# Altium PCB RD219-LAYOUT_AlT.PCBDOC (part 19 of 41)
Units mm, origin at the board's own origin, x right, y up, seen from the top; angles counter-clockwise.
Board outline 209.75 x 159.97 mm, 2 copper layers (TOP, BOTTOM), stack 0 mm thick; 398 components, 199 nets, 1469 pads, 0 vias.
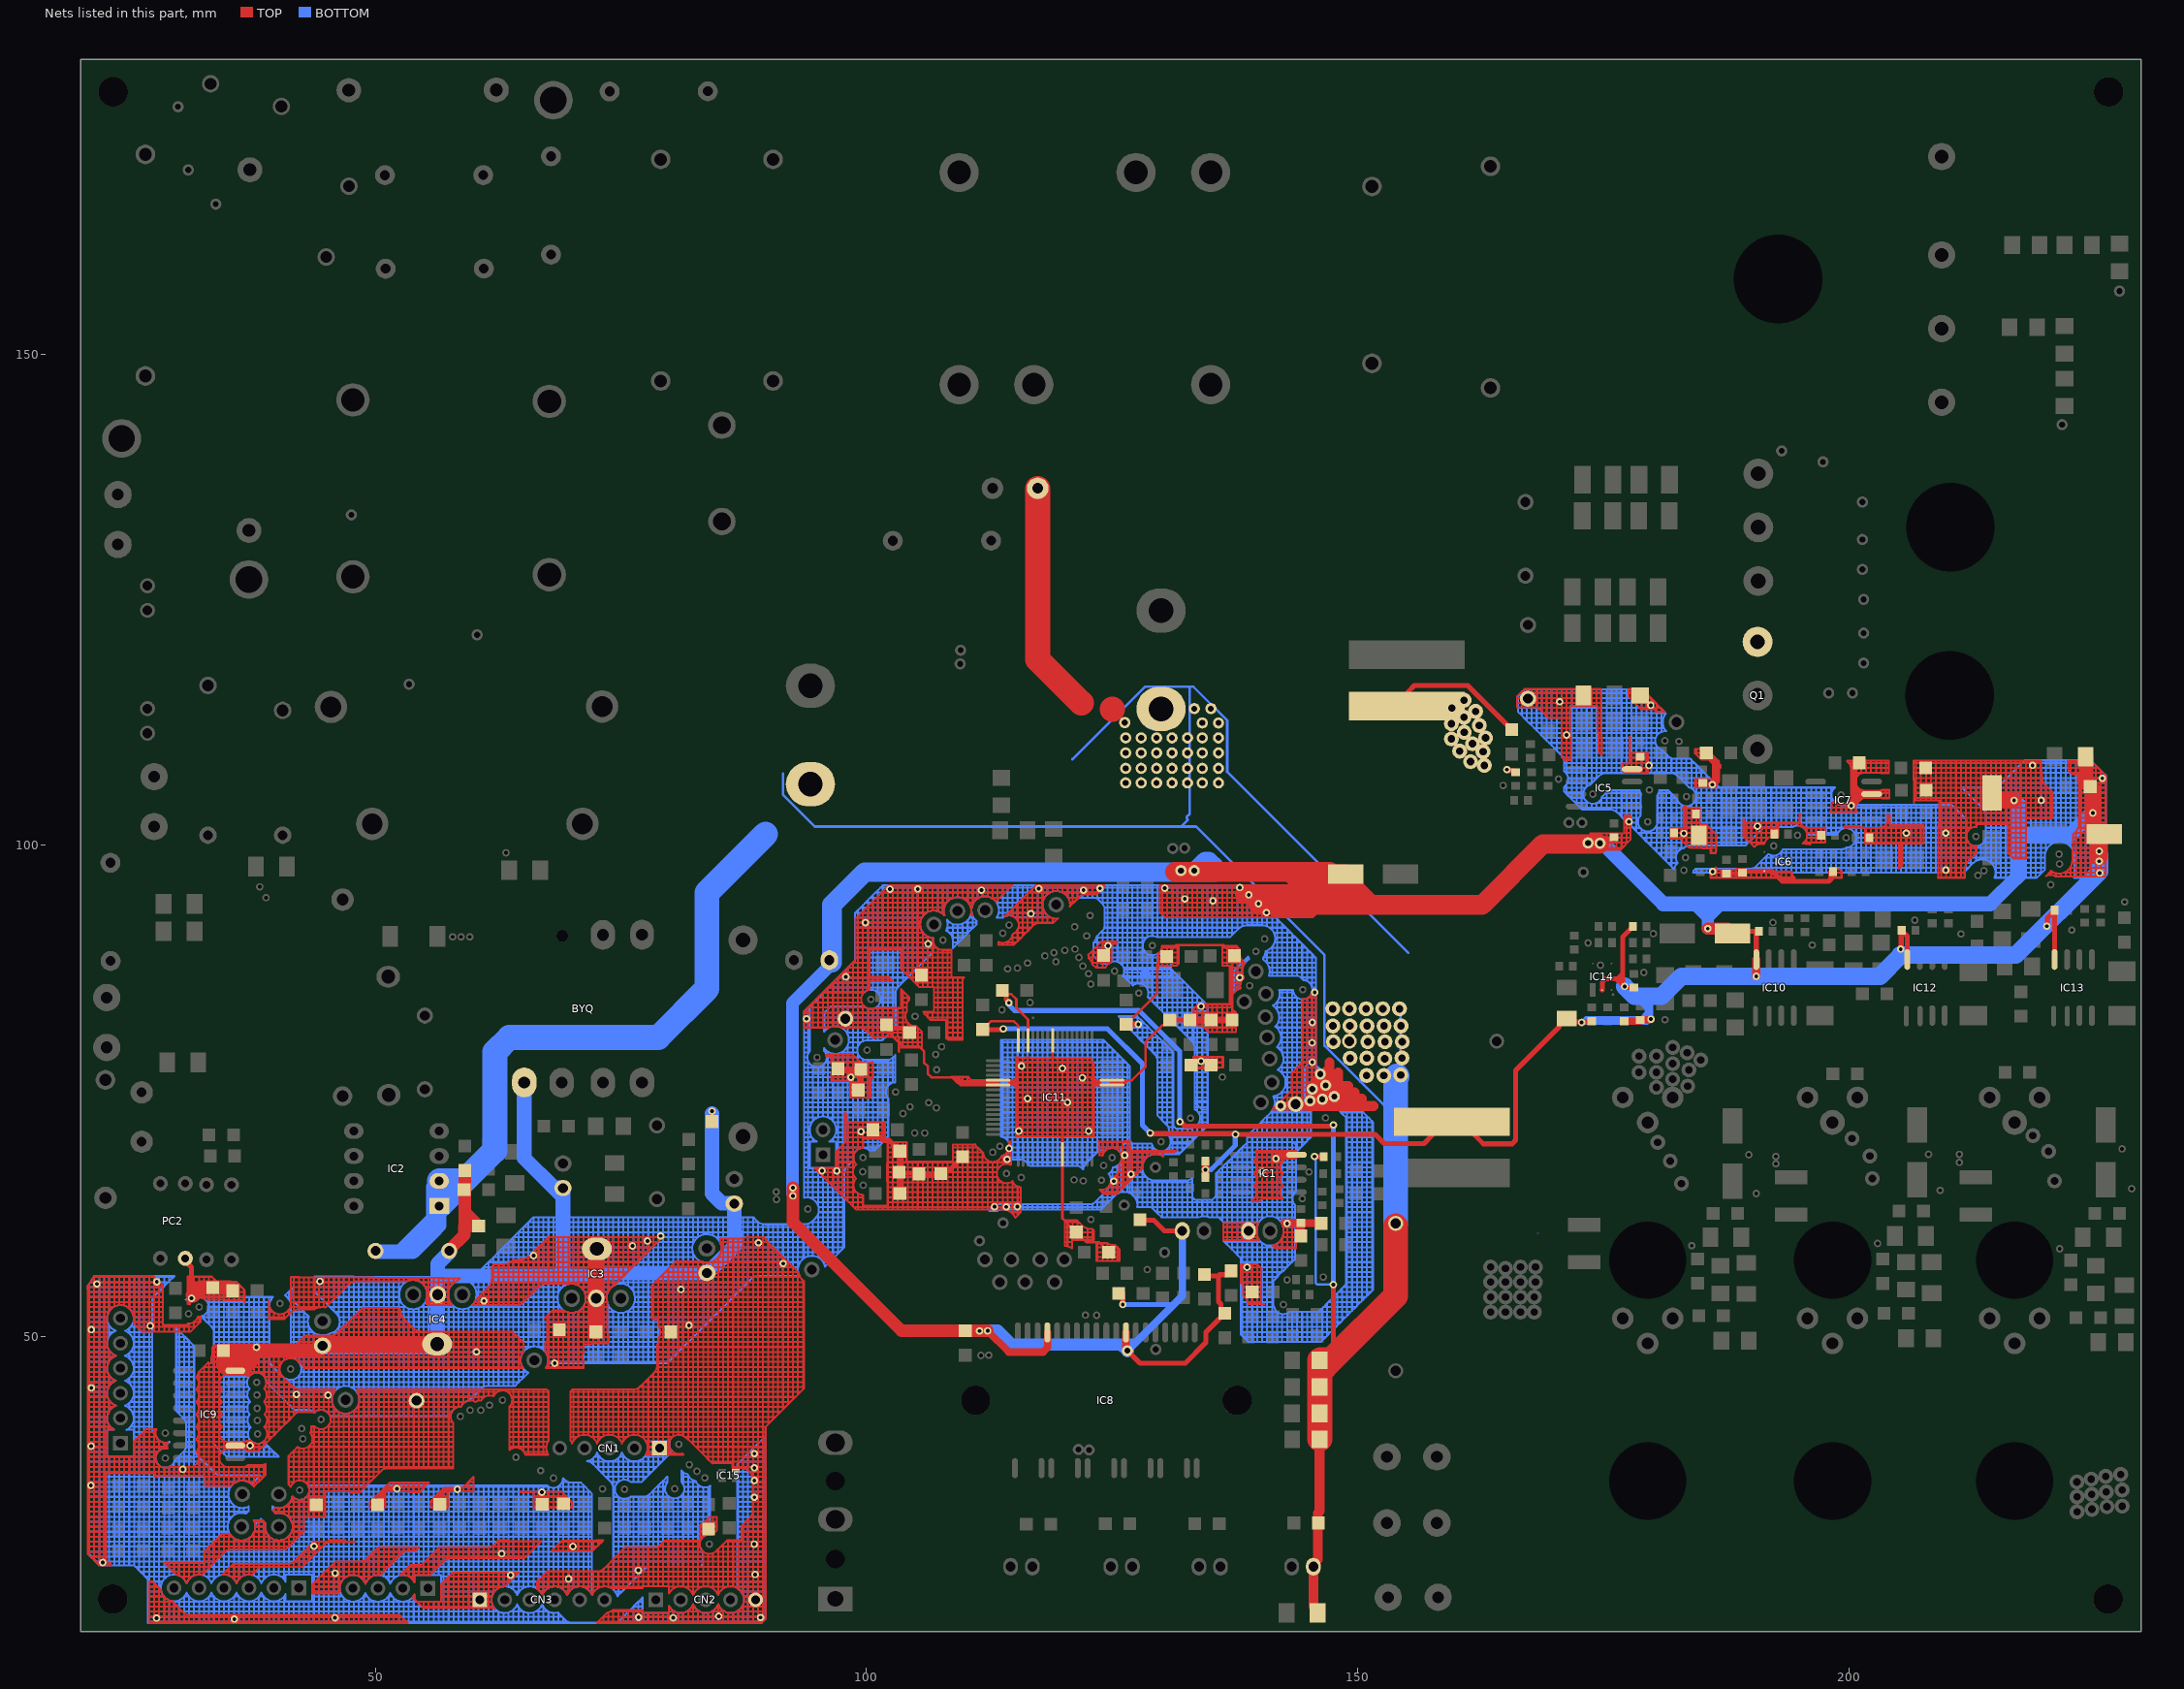
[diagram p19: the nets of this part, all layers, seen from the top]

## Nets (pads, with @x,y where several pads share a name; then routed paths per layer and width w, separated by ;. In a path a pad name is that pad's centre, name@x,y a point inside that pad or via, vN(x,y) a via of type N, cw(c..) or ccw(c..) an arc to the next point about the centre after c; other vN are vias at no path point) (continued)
GND: (continued)
  BOTTOM w0.203: 20.889,27.877 20.889,28.128 ; 21.318,56.068 21.397,56.068 ; 22.765,41.344 ccw(c24.064,41.717) 22.767,41.336 ; 22.765,43.884 ccw(c24.064,44.257) 22.767,43.876 ; 22.765,46.424 ccw(c24.064,46.797) 22.767,46.416 ; 22.765,48.964 ccw(c24.064,49.337) 22.767,48.956 ; 22.765,51.504 ccw(c24.064,51.877) 22.767,51.496 ; 22.771,41.322 cw(c24.064,41.717) 22.767,41.336 ; 22.771,43.862 cw(c24.064,44.257) 22.767,43.876 ; 22.771,46.402 cw(c24.064,46.797) 22.767,46.416 ; 22.771,48.942 cw(c24.064,49.337) 22.767,48.956 ; 22.771,51.482 cw(c24.064,51.877) 22.767,51.496 ; 22.918,52.593 ccw(c24.064,51.877) 22.871,52.512 ; 22.921,52.598 22.921,53.02 ; 22.93,52.613 cw(c24.064,51.877) 23.343,53.02 ; 23.409,40.535 cw(c24.064,41.717) 23.046,40.828 ; 23.42,40.529 22.921,40.529 ; 23.923,53.221 cw(c24.064,51.877) 23.937,53.223 ; 23.946,53.223 ccw(c24.064,51.877) 23.937,53.223 ; 24.699,40.524 ccw(c24.064,41.717) 24.708,40.529 ; 25.068,40.813 cw(c24.064,41.717) 24.953,40.699 ; 25.082,40.828 25.461,40.828 ; 25.084,40.83 ccw(c24.064,41.717) 25.361,41.336 ; 25.357,46.402 cw(c24.064,46.797) 25.082,45.908 ; 25.361,46.416 25.461,46.416 ; 25.363,46.424 ccw(c24.064,46.797) 25.416,46.797 ccw(c24.064,46.797) 25.41,46.924 ; 27.526,40.099 cw(c28.128,40.701) 27.493,40.134 ; 27.527,54.131 27.94,54.544 ; 27.536,40.088 cw(c28.128,40.701) 27.528,40.097 ; 27.661,37.773 ccw(c28.636,37.653) 27.73,37.272 ; 27.662,37.78 27.493,37.78 ; 27.663,37.79 cw(c28.636,37.653) 27.886,38.288 ; 27.687,39.939 ccw(c28.636,40.193) 27.687,39.937 ; 28.332,25.08 ccw(c29.525,24.445) 28.179,24.572 ; 28.382,38.602 ccw(c28.636,37.653) 28.38,38.602 ; 28.505,25.332 ccw(c29.525,24.445) 28.332,25.08 28.001,25.08 ; 28.509,25.336 28.509,25.588 ; 28.509,38.73 28.509,38.796 ; 28.509,56.172 28.509,56.068 ; 28.521,25.349 cw(c29.525,24.445) 28.804,25.588 ; 28.575,38.796 28.509,38.796 ; 29.051,36.762 ccw(c28.636,37.653) 29.055,36.764 ; 29.051,39.302 cw(c28.636,40.193) 28.509,39.219 ; 29.054,39.276 28.38,38.602 ; 29.067,36.77 cw(c28.636,37.653) 29.055,36.764 ; 29.464,56.068 29.017,56.068 ; 29.585,37.399 cw(c28.636,37.653) 29.585,37.397 ; 30.241,25.591 ccw(c29.525,24.445) 30.033,25.698 ; 30.246,25.588 30.541,25.588 ; 30.261,25.579 cw(c29.525,24.445) 30.541,25.336 ; 30.507,38.32 30.475,38.288 ; 30.507,41.685 30.348,41.844 ; 30.701,53.754 pad.@30.983,54.036 ; 30.718,53.754 pad.@31.049,53.754 ; 31.045,25.332 ccw(c32.065,24.445) 30.872,25.08 ; 31.049,25.336 31.049,25.588 ; 31.061,25.349 cw(c32.065,24.445) 31.344,25.588 ; pad.@31.412,53.754 pad.@31.049,53.754 ; pad.@31.414,53.756 cw(c32.071,53.026) pad.@31.557,53.863 ; 32.781,25.591 ccw(c32.065,24.445) 32.573,25.698 ; 32.786,25.588 33.081,25.588 ; 32.801,25.579 cw(c32.065,24.445) 33.081,25.336 ; 32.904,52.505 ccw(c32.071,53.026) 32.909,52.512 ; 32.913,52.519 cw(c32.071,53.026) 32.909,52.512 ; 33.585,25.332 ccw(c34.605,24.445) 33.412,25.08 ; 33.589,25.336 33.589,25.588 ; 33.601,25.349 cw(c34.605,24.445) 33.884,25.588 ; 35.109,33.607 cw(c36.463,33.97) 35.085,33.716 ; 35.113,30.076 cw(c36.383,30.668) 35.077,30.16 ; 35.113,31.26 ccw(c36.383,30.668) 35.077,31.176 ; 35.113,33.593 35.113,33.208 ; 35.116,33.584 ccw(c36.463,33.97) 35.287,33.208 ; 35.321,25.591 ccw(c34.605,24.445) 35.113,25.698 ; 35.326,25.588 35.621,25.588 ; 35.341,25.579 cw(c34.605,24.445) 35.621,25.336 ; 35.62,31.843 ccw(c36.383,30.668) 35.417,31.684 ; 35.621,31.844 35.621,32.192 ; 35.64,31.857 cw(c36.383,30.668) 36.129,32.046 ; 35.871,32.7 ccw(c36.463,33.97) 36.124,32.61 ccw(c36.463,33.97) 36.129,32.609 ; 36.116,29.292 cw(c36.383,30.668) 35.621,29.492 ; 36.116,32.044 cw(c36.383,30.668) 36.129,32.046 ; 36.125,25.332 ccw(c37.145,24.445) 35.952,25.08 ; 36.129,25.336 36.129,25.588 ; 36.129,29.29 36.129,29.144 ; 36.14,29.288 ccw(c36.383,30.668) 36.637,29.29 ; 36.14,32.048 ccw(c36.383,30.668) 36.129,32.046 ; 36.141,25.349 cw(c37.145,24.445) 36.424,25.588 ; 36.839,31.993 ccw(c36.383,30.668) 36.637,32.046 ; 36.843,31.992 37.044,32.192 ; 37.022,41.348 cw(c37.995,41.485) 37.081,41.844 ; 37.025,41.331 ccw(c37.995,41.485) 37.145,40.992 ; 37.024,41.336 36.637,41.336 ; 37.121,32.732 cw(c36.463,33.97) 37.115,32.729 ; 37.145,45.951 cw(c37.93,45.359) 37.653,46.302 ; 37.203,44.694 ccw(c37.967,44.076) 37.145,44.615 ; 37.209,42.094 cw(c37.973,42.712) 37.145,42.183 ; 37.212,44.689 cw(c37.93,45.359) 37.145,44.769 ; 37.221,42.09 ccw(c37.995,41.485) 37.145,41.978 ; 37.26,43.393 cw(c37.967,44.076) 37.145,43.537 ; 37.266,43.395 ccw(c37.973,42.712) 37.241,43.368 ; 37.305,40.78 ccw(c38.024,40.11) 37.145,40.55 ; 37.312,40.778 cw(c37.995,41.485) 37.264,40.828 ; 37.401,35.012 ccw(c36.463,33.97) 37.145,35.194 ; 37.406,35.007 37.639,35.24 ; 37.653,30.076 ccw(c36.383,30.668) 37.689,30.16 ; 37.771,30.863 cw(c36.383,30.668) 37.772,30.859 ; 37.861,25.591 ccw(c37.145,24.445) 37.653,25.698 ; 37.866,25.588 38.161,25.588 ; 37.881,25.579 cw(c37.145,24.445) 38.161,25.336 ; 38.147,35.748 37.653,35.748 ; 38.151,46.317 cw(c37.93,45.359) 38.161,46.314 ; 38.16,39.137 cw(c38.024,40.11) 37.655,39.199 cw(c38.024,40.11) 37.653,39.2 ; 38.168,46.313 ccw(c37.93,45.359) 38.161,46.314 ; 38.359,31.446 38.161,31.249 ; 38.371,31.459 38.655,31.176 ; 38.628,39.336 cw(c38.024,40.11) 38.625,39.333 ; 38.665,25.332 ccw(c39.685,24.445) 38.492,25.08 ; 38.669,25.336 38.669,25.588 ; 38.681,25.349 cw(c39.685,24.445) 38.964,25.588 ; 38.822,30.959 ccw(c40.193,30.668) 38.791,30.668 ; 38.827,30.983 cw(c40.193,30.668) 38.831,30.999 ; 38.833,31.007 ccw(c40.193,30.668) 38.831,30.999 ; 38.885,30.166 ccw(c40.193,30.668) 38.887,30.16 ; 38.893,30.143 cw(c40.193,30.668) 38.887,30.16 ; 38.912,45.408 39.177,45.143 ; 38.911,45.411 ccw(c37.93,45.359) 38.745,45.908 ; 38.92,45.4 39.177,45.4 ; 39.168,29.712 cw(c40.193,30.668) 38.887,30.16 ; 39.177,29.702 39.177,29.652 ; 39.185,29.694 ccw(c40.193,30.668) 39.227,29.652 ; 39.322,53.613 ccw(c40.32,53.147) 39.286,53.528 ; 39.33,53.63 cw(c40.32,53.147) 39.362,53.692 ; 39.362,53.69 cw(c40.296,53.386) 39.362,53.692 ; 39.366,53.698 ccw(c40.32,53.147) 39.362,53.692 ; 39.525,32.738 39.525,32.367 39.685,32.206 ; 39.535,32.732 ccw(c40.193,33.97) 39.685,32.664 ; 39.542,46.99 39.608,46.924 ; 39.59,54.069 ccw(c40.296,53.386) 39.559,54.036 ; 39.594,54.073 39.177,54.073 ; 39.854,32.028 cw(c40.193,30.668) 39.862,32.03 ; 40.401,25.591 ccw(c39.685,24.445) 40.193,25.698 ; 40.406,25.588 40.701,25.588 ; 40.421,25.579 cw(c39.685,24.445) 40.701,25.336 ; 40.785,32.7 cw(c40.193,33.97) 40.701,32.664 ; 40.817,54.22 cw(c40.296,53.386) 41.034,54.036 ; 40.878,23.81 cw(c39.685,24.445) 40.873,23.801 ; 40.878,25.08 ccw(c39.685,24.445) 40.873,25.089 ; 40.923,54.324 41.143,54.544 ; 41.151,53.87 cw(c40.32,53.147) 41.153,53.868 ; 41.156,53.863 ccw(c40.296,53.386) 41.153,53.868 ; 41.201,31.642 ccw(c40.193,30.668) 41.159,31.684 ; 41.209,31.634 41.209,31.684 ; 41.209,54.61 41.209,54.544 ; 41.218,31.624 cw(c40.193,30.668) 41.499,31.176 ; 41.493,30.143 cw(c40.193,30.668) 41.209,29.702 ; 41.499,30.16 41.717,30.16 ; 41.502,30.166 ccw(c40.193,30.668) 41.595,30.668 ; 41.573,33.727 cw(c40.193,33.97) 41.369,33.208 ; 41.577,33.732 ccw(c42.307,34.389) 41.717,33.604 ; 41.717,42.603 41.717,42.86 ; 41.955,53.329 42.225,53.059 ; 42.264,53.02 42.225,53.02 ; 43.149,51.508 ccw(c44.575,51.583) 43.15,51.496 ; 43.151,51.483 cw(c44.575,51.583) 43.15,51.496 ; 43.166,34.866 43.241,34.866 ; 43.167,34.866 cw(c42.307,34.389) 43.228,34.732 ; 43.225,52.048 ccw(c44.575,51.583) 43.211,52.004 ; 43.228,52.056 42.772,52.512 ; 43.715,42.352 43.749,42.352 ; 43.749,42.318 43.749,42.352 ; 43.785,42.282 43.708,42.359 ; 43.788,42.285 cw(c44.482,41.59) 43.862,42.352 ; 44.257,54.143 44.257,54.544 ; 44.257,56.12 44.257,56.068 ; 44.765,53.635 44.765,54.036 ; 45.4,41.942 ccw(c44.482,41.59) 45.273,42.173 ; 45.401,41.938 45.781,41.938 ; 45.445,50.368 ccw(c45.273,51.456) 45.452,50.369 ; 45.458,50.373 cw(c44.702,51.583) 45.452,50.369 ; 45.773,50.474 cw(c45.273,51.456) 45.452,50.369 ; 45.778,42.855 ccw(c46.979,43.576) 45.781,42.849 ; 45.778,44.298 ccw(c46.979,43.576) 45.61,43.876 ; 45.781,44.304 45.781,44.384 ; 45.781,50.479 45.781,49.972 ; 45.784,50.48 46.289,50.48 ; 45.79,42.834 cw(c46.979,43.576) 45.781,42.849 ; 45.79,44.319 cw(c46.979,43.576) 45.833,44.384 ; 45.79,50.483 ccw(c45.273,51.456) 46.27,50.988 ; 46.278,42.363 cw(c46.979,43.576) 45.781,42.849 ; 46.289,42.357 46.289,42.352 ; 46.297,42.352 46.289,42.352 ; 46.3,42.351 ccw(c46.979,43.576) 46.797,42.187 ; 46.387,24.562 ccw(c47.729,24.397) 46.419,24.064 ; 46.389,24.572 46.289,24.572 ; 46.39,24.585 cw(c47.729,24.397) 46.443,24.815 ; 46.417,24.07 ccw(c47.729,24.397) 46.419,24.064 ; 46.423,24.047 cw(c47.729,24.397) 46.419,24.064 ; 46.436,24.792 cw(c47.729,24.397) 46.558,25.073 cw(c47.729,24.397) 46.562,25.08 ; 46.784,44.964 cw(c46.979,43.576) 46.797,44.966 ; 46.79,25.369 ccw(c47.729,24.397) 46.562,25.08 ; 46.797,25.376 46.797,25.588 ; 46.807,25.386 cw(c47.729,24.397) 47.09,25.588 ; 46.808,44.968 ccw(c46.979,43.576) 46.797,44.966 ; 47.289,23.119 cw(c47.729,24.397) 46.797,23.418 ; 47.294,42.211 ccw(c46.979,43.576) 47.305,42.213 ; 47.305,23.114 47.305,23.048 ; 47.311,23.112 ccw(c47.729,24.397) 47.645,23.048 ; 47.318,42.217 cw(c46.979,43.576) 47.305,42.213 ; 47.458,44.894 ccw(c46.979,43.576) 47.305,44.94 ; 47.463,44.892 47.813,44.892 ; 47.481,44.885 cw(c46.979,43.576) 47.813,44.703 ; 47.8,25.747 cw(c47.729,24.397) 47.813,25.746 ; 47.803,42.443 cw(c46.979,43.576) 47.661,42.352 ; 47.812,23.048 cw(c47.729,24.397) 47.645,23.048 ; 47.813,42.45 47.813,42.352 ; 47.823,25.745 ccw(c47.729,24.397) 47.813,25.746 ; 47.823,42.457 ccw(c46.979,43.576) 48.184,42.86 ; 48.18,42.855 ccw(c46.979,43.576) 48.184,42.86 ; 48.193,42.876 cw(c46.979,43.576) 48.184,42.86 ; 48.363,25.59 ccw(c47.729,24.397) 48.321,25.612 ; 48.368,25.588 48.829,25.588 ; 48.384,25.579 cw(c47.729,24.397) 48.829,25.182 ; 48.822,23.603 ccw(c47.729,24.397) 48.829,23.612 ; 48.836,23.622 cw(c47.729,24.397) 48.829,23.612 ; 48.991,23.913 cw(c47.729,24.397) 48.829,23.612 ; 48.999,23.935 ccw(c50.269,24.397) 49.211,23.556 ; 49.33,25.369 ccw(c50.269,24.397) 49.102,25.08 ; 49.337,25.376 49.337,25.588 ; 49.347,25.386 cw(c50.269,24.397) 49.63,25.588 ; 49.829,23.119 cw(c50.269,24.397) 49.337,23.418 ; 49.845,23.114 49.845,23.048 ; 49.851,23.112 ccw(c50.269,24.397) 50.185,23.048 ; 50.34,25.747 cw(c50.269,24.397) 50.353,25.746 ; 50.352,23.048 cw(c50.269,24.397) 50.185,23.048 ; 50.363,25.745 ccw(c50.269,24.397) 50.353,25.746 ; 50.903,25.59 ccw(c50.269,24.397) 50.861,25.612 ; 50.908,25.588 51.369,25.588 ; 50.924,25.579 cw(c50.269,24.397) 51.369,25.182 ; 51.362,23.603 ccw(c50.269,24.397) 51.369,23.612 ; 51.376,23.622 cw(c50.269,24.397) 51.369,23.612 ; 51.531,23.913 cw(c50.269,24.397) 51.369,23.612 ; 51.539,23.935 ccw(c52.809,24.397) 51.744,23.565 ccw(c52.809,24.397) 51.751,23.556 ; 51.87,25.369 ccw(c52.809,24.397) 51.642,25.08 ; 51.877,25.376 51.877,25.588 ; 51.887,25.386 cw(c52.809,24.397) 52.17,25.588 ; 52.369,23.119 cw(c52.809,24.397) 51.877,23.418 ; 52.385,23.114 52.385,23.048 ; 52.391,23.112 ccw(c52.809,24.397) 52.725,23.048 ; 52.88,25.747 cw(c52.809,24.397) 52.893,25.746 ; 52.889,55.397 ccw(c53.862,54.354) 52.618,55.052 ; 52.892,23.048 cw(c52.809,24.397) 52.725,23.048 ; 52.893,55.401 52.893,55.56 ; 52.903,25.745 ccw(c52.809,24.397) 52.893,25.746 ; 52.907,55.414 cw(c53.862,54.354) 53.1,55.56 ; 53.085,53.03 cw(c53.862,54.227) 52.893,53.179 ; 53.1,53.02 52.893,53.02 ; 53.106,53.016 ccw(c53.862,54.227) 53.397,52.877 ccw(c53.862,54.227) 53.401,52.876 ; 53.443,25.59 ccw(c52.809,24.397) 53.401,25.612 ; 53.448,25.588 53.909,25.588 ; 53.464,25.579 cw(c52.809,24.397) 53.909,25.182 ; 54.002,23.762 cw(c52.809,24.397) 53.997,23.753 ; 54.002,25.032 ccw(c52.809,24.397) 53.997,25.041 ; 57.675,41.938 57.465,41.938 ; 57.675,41.946 cw(c58.656,41.895) 57.786,42.352 ; 57.964,55.463 ccw(c58.862,54.354) 57.618,55.052 ; 57.973,55.47 57.973,55.56 ; 57.974,42.602 cw(c58.656,41.895) 58.471,42.86 ; 57.983,55.478 cw(c58.862,54.354) 58.1,55.56 ; 58.469,52.855 cw(c58.862,54.227) 58.1,53.02 ; 58.481,52.851 58.481,52.512 ; 58.493,52.848 ccw(c58.862,54.227) 58.989,52.805 ; 58.725,42.875 ccw(c58.656,41.895) 58.486,42.863 ccw(c58.656,41.895) 58.481,42.862 ; 58.729,42.882 cw(c59.646,42.53) 58.989,43.261 ; 58.986,52.805 ccw(c58.862,54.227) 58.989,52.805 ; 59.011,52.807 cw(c58.862,54.227) 58.989,52.805 ; 59.125,43.363 cw(c59.646,42.53) 59.133,43.368 ; 59.14,43.372 ccw(c59.646,42.53) 59.133,43.368 ; 59.595,43.511 ccw(c59.646,42.53) 59.497,43.501 ; 59.597,43.511 59.962,43.876 ; 61.842,23.053 ccw(c63.18,23.241) 61.842,23.048 ; 61.845,23.03 cw(c63.18,23.241) 61.842,23.048 ; 62.545,22.048 ccw(c63.18,23.241) 62.576,22.032 ; 63.039,24.585 cw(c63.18,23.241) 63.053,24.587 ; 63.062,24.587 ccw(c63.18,23.241) 63.053,24.587 ; 63.553,21.942 ccw(c63.18,23.241) 63.561,21.944 ; 63.575,21.948 cw(c63.18,23.241) 63.561,21.944 ; 63.773,22.026 cw(c63.18,23.241) 63.561,21.944 ; 63.784,22.032 64.069,22.032 ; 63.794,22.037 ccw(c63.18,23.241) 64.069,22.223 ; 64.067,22.221 ccw(c63.18,23.241) 64.069,22.223 ; 64.084,22.237 cw(c63.18,23.241) 64.069,22.223 ; 64.245,24.073 ccw(c63.18,23.241) 64.069,24.259 ; 64.252,24.064 64.577,24.064 ; 64.259,24.054 cw(c63.18,23.241) 64.45,23.704 cw(c65.72,23.241) 64.574,23.957 cw(c65.72,23.241) 64.577,23.962 ; 65.085,22.048 ccw(c65.72,23.241) 65.116,22.032 ; 65.086,46.747 ccw(c66.19,47.61) 65.457,46.416 ; 65.086,48.473 cw(c66.19,47.61) 65.593,48.878 ; 65.576,46.351 cw(c66.19,47.61) 65.457,46.416 ; 65.579,24.585 cw(c65.72,23.241) 65.593,24.587 ; 65.582,46.347 65.143,45.908 ; 65.602,24.587 ccw(c65.72,23.241) 65.593,24.587 ; 65.78,48.951 cw(c66.19,47.61) 65.798,48.956 ; 65.804,48.958 ccw(c66.19,47.61) 65.798,48.956 ; 66.093,21.942 ccw(c65.72,23.241) 66.101,21.944 ; 66.115,21.948 cw(c65.72,23.241) 66.101,21.944 ; 66.313,22.026 cw(c65.72,23.241) 66.101,21.944 ; 66.324,22.032 66.609,22.032 ; 66.334,22.037 ccw(c65.72,23.241) 66.609,22.223 ; 66.607,22.221 ccw(c65.72,23.241) 66.609,22.223 ; 66.624,22.237 cw(c65.72,23.241) 66.609,22.223 ; 66.785,24.073 ccw(c65.72,23.241) 66.609,24.259 ; 66.792,24.064 67.117,24.064 ; 66.799,24.054 cw(c65.72,23.241) 66.99,23.704 cw(c68.26,23.241) 67.114,23.957 ; 67.117,23.962 67.117,24.064 ; 67.126,23.977 cw(c68.26,23.241) 67.188,24.064 ; 67.5,34.866 67.117,34.866 ; 67.502,34.865 ccw(c68.133,35.618) 67.625,34.777 ; 67.625,22.048 ccw(c68.26,23.241) 67.656,22.032 ; 68.119,24.585 cw(c68.26,23.241) 68.133,24.587 ; 68.142,24.587 ccw(c68.26,23.241) 68.133,24.587 ; 68.61,21.935 cw(c68.26,23.241) 68.599,21.933 ; 68.641,21.891 68.641,21.524 ; 69.116,35.618 cw(c68.133,35.618) 69.04,35.24 ; 69.116,35.62 69.149,35.587 ; 69.258,35.478 69.149,35.587 ; 69.325,24.073 ccw(c68.26,23.241) 69.149,24.259 ; 69.332,24.064 69.657,24.064 ; 69.339,24.054 cw(c68.26,23.241) 69.53,23.704 cw(c70.8,23.241) 69.654,23.957 cw(c70.8,23.241) 69.657,23.962 ; 69.646,52.461 ccw(c69.991,53.846) 69.657,52.458 ; 69.67,52.455 cw(c69.991,53.846) 69.657,52.458 ; 70.908,55.066 cw(c69.991,53.973) 70.924,55.052 ; 70.927,55.05 ccw(c69.991,53.973) 70.924,55.052 ; 71.174,53.047 ccw(c69.991,53.846) 71.181,53.058 ; 71.188,53.068 cw(c69.991,53.846) 71.181,53.058 ; 71.566,37.342 ccw(c71.308,38.669) 71.77,37.399 ccw(c71.308,38.669) 72.197,37.651 ; 72.034,23.86 72.034,24.064 ; 72.035,23.791 ccw(c70.8,23.241) 71.872,24.064 ; 73.213,37.476 ccw(c73.848,38.669) 73.721,37.323 ; 73.913,35.292 73.721,35.484 ; 74.214,52.649 cw(c74.991,53.846) 73.827,53.02 ; 74.227,24.261 cw(c73.34,23.241) 74.237,24.252 ; 74.229,52.639 74.229,52.512 ; 74.235,52.635 ccw(c74.991,53.846) 74.48,52.513 ccw(c74.991,53.846) 74.483,52.512 ; 74.639,23.614 ccw(c73.34,23.241) 74.412,24.064 ; 74.642,23.603 74.737,23.697 ; 75.239,52.44 ccw(c74.991,53.846) 75.245,52.441 ; 75.245,21.51 75.245,21.016 ; 75.263,52.445 cw(c74.991,53.846) 75.245,52.441 ; 75.753,37.476 ccw(c76.388,38.669) 76.261,37.323 ; 75.908,55.066 cw(c74.991,53.973) 75.924,55.052 ; 75.927,55.05 ccw(c74.991,53.973) 75.924,55.052 ; 76.029,33.748 cw(c75.372,34.478) 75.992,33.716 ; 76.029,35.208 ccw(c75.372,34.478) 75.992,35.24 ; 76.031,33.749 76.261,33.749 ; 76.031,35.207 76.261,35.207 ; 76.12,25.08 75.753,25.08 ; 76.146,53.007 cw(c74.991,53.846) 75.753,52.639 ; 76.155,53.02 76.261,53.02 ; 76.16,53.027 ccw(c74.991,53.846) 76.261,53.195 ; 76.253,25.214 75.753,24.713 ; 76.254,25.214 76.261,25.221 ; 77.136,35.24 76.769,35.24 ; 77.559,39.345 cw(c76.388,38.669) 77.563,39.337 ; 77.666,38.229 cw(c76.388,38.669) 77.406,37.78 ; 77.673,38.251 ccw(c76.388,38.669) 77.685,38.288 ; 79.676,37.78 79.309,37.78 ; 79.723,35.165 ccw(c80.475,34.534) 79.514,34.738 ccw(c80.475,34.534) 79.513,34.732 ; 79.723,35.166 79.723,35.24 ; 79.894,22.606 ccw(c81.087,23.241) 79.899,22.597 ; 80.184,38.288 79.817,38.288 ; 80.19,38.295 79.817,37.921 ; 80.225,38.332 cw(c80.895,39.051) 79.946,38.796 ; 81.01,33.709 cw(c80.475,34.534) 80.833,33.618 ; 81.02,33.716 81.341,33.716 ; 81.025,33.719 ccw(c80.475,34.534) 81.341,34.069 ; 81.181,35.218 81.181,35.24 ; 81.181,36.389 81.181,36.256 ; 81.182,35.216 cw(c80.475,34.534) 81.341,34.998 ; 81.182,36.387 ccw(c81.967,36.978) 81.301,36.256 ; 81.796,36.011 cw(c81.967,36.978) 81.341,36.221 ; 81.802,36.007 ccw(c82.737,36.311) 81.849,35.89 ; 82.233,22.525 cw(c81.087,23.241) 81.849,22.125 ; 82.243,22.54 82.357,22.54 ; 82.246,22.545 ccw(c81.087,23.241) 82.357,22.778 ; 82.617,35.335 cw(c82.737,36.311) 82.357,35.405 ; 82.617,35.339 ccw(c83.551,35.642) 82.655,35.24 ; 82.856,34.948 cw(c83.551,35.642) 82.655,35.24 ; 82.865,34.939 82.865,34.732 ; 82.869,34.936 ccw(c83.551,35.642) 83.182,34.732 ; 83.325,28.183 cw(c84.008,28.89) 83.059,28.636 ; 83.328,28.18 83.328,28.128 ; 84.101,34.828 cw(c83.551,35.642) 84.092,34.822 ; 84.773,22.525 cw(c83.627,23.241) 84.389,22.125 ; 84.783,22.54 84.897,22.54 ; 84.786,22.545 ccw(c83.627,23.241) 84.897,22.778 ; 84.895,59.925 ccw(c83.818,58.989) 84.676,60.129 ccw(c83.818,58.989) 84.672,60.132 ; 84.897,59.922 84.897,60.132 ; 84.911,59.906 cw(c83.818,58.989) 85.096,59.624 ; 85.392,22.134 cw(c86.167,23.241) 85.011,22.54 ; 85.405,22.125 85.405,22.032 ; 85.411,22.12 ccw(c86.167,23.241) 85.563,22.032 ; 86.843,24.412 cw(c86.167,23.241) 86.846,24.41 ; 86.929,37.11 86.929,36.764 ; 87.232,24.073 ccw(c86.167,23.241) 86.929,24.357 ; 87.239,24.064 87.437,24.064 ; 87.246,24.054 cw(c86.167,23.241) 87.437,23.704 ; 87.313,22.525 cw(c86.167,23.241) 86.929,22.125 ; 87.323,22.54 87.437,22.54 ; 87.326,22.545 ccw(c86.167,23.241) 87.437,22.778 ; 93.184,56.172 cw(c94.422,56.83) 93.044,56.576 ; 93.19,56.162 93.025,56.162 ; 93.657,64.136 cw(c93.914,62.926) 93.66,64.136 ; 94.235,79.076 ccw(c94.965,78.418) 94.125,78.928 ; 94.236,79.077 94.236,79.436 ; 94.55,77.528 ccw(c94.965,78.418) 94.965,77.435 ccw(c94.965,78.418) 95.057,77.44 ; 94.91,69.872 cw(c95.565,71.054) 94.549,70.163 ; 94.921,69.866 94.549,69.866 ; 95.052,63.409 cw(c93.914,62.926) 95.057,63.398 ; 95.061,63.389 ccw(c93.914,62.926) 95.057,63.398 ; 95.124,62.669 ccw(c93.914,62.926) 95.124,62.672 ; 95.128,62.69 cw(c93.914,62.926) 95.124,62.672 ; 95.69,79.347 ccw(c96.809,80.19) 95.693,79.342 ; 95.693,79.077 95.693,79.342 ; 95.693,81.039 95.693,81.468 ; 95.695,79.076 cw(c94.965,78.418) 95.805,78.928 ; 95.705,81.053 cw(c96.809,80.19) 96.073,81.383 ; 96.2,69.861 ccw(c95.565,71.054) 96.209,69.866 ; 96.234,57.592 96.073,57.592 ; 96.566,78.81 cw(c96.809,80.19) 96.2,78.928 ; 96.581,78.807 96.581,78.42 ; 96.59,78.806 ccw(c96.809,80.19) 97.089,78.817 ; 97.077,81.566 cw(c96.809,80.19) 97.089,81.564 ; 97.101,81.561 ccw(c96.809,80.19) 97.089,81.564 ; 97.593,81.352 ccw(c96.809,80.19) 97.385,81.468 ; 97.597,81.35 97.597,81.468 ; 97.613,81.338 cw(c96.809,80.19) 97.981,80.96 ; 98.099,80.738 cw(c96.809,80.19) 98.105,80.725 ; 98.109,80.715 ccw(c96.809,80.19) 98.105,80.725 ; 98.185,79.923 cw(c96.809,80.19) 98.105,79.656 ; 98.189,79.944 98.613,79.944 ; 98.19,79.947 ccw(c96.809,80.19) 98.211,80.19 ccw(c96.809,80.19) 98.186,80.452 ; 98.66,68.253 ccw(c99.642,68.236) 98.695,67.975 ; 98.66,68.26 98.613,68.26 ; 98.66,68.27 cw(c99.642,68.236) 98.816,68.768 ; 98.698,67.965 cw(c99.642,68.236) 98.695,67.975 ; 98.867,93.152 99.121,93.152 ; 99.784,83.605 99.629,83.605 ; 99.784,85.062 99.629,85.062 ; 99.786,83.604 ccw(c100.444,84.334) 99.924,83.5 ; 99.786,85.064 cw(c100.444,84.334) 100.137,85.267 ; 100.3,68.966 ccw(c99.642,68.236) 100.137,69.085 ; 100.301,68.965 100.645,68.965 ; 100.964,83.501 ccw(c100.444,84.334) 101.15,83.651 ccw(c100.444,84.334) 101.153,83.654 ; 101.367,83.998 cw(c100.444,84.334) 101.153,83.654 ; 101.371,84.008 101.661,84.008 ; 101.373,84.014 ccw(c100.444,84.334) 101.426,84.334 ccw(c100.444,84.334) 101.409,84.516 ; 101.971,74.872 ccw(c102.953,74.907) 101.971,74.864 ; 101.972,74.855 cw(c102.953,74.907) 101.971,74.864 ; 102.223,74.249 cw(c102.953,74.907) 102.169,74.314 ; 102.224,74.248 102.224,73.848 ; 102.735,78.458 102.941,78.665 102.941,78.42 ; 102.912,81.468 102.677,81.468 ; 102.936,75.889 ccw(c102.953,74.907) 102.818,75.88 ; 102.941,75.889 102.941,76.388 ; 103.24,85.606 103.674,86.04 ; 105.467,92.137 cw(c106.858,91.966) 105.631,92.644 ; 105.724,91.143 cw(c106.858,91.966) 105.498,91.627 ; 105.724,92.79 ccw(c106.858,91.966) 105.631,92.644 ; 106.222,90.718 cw(c106.858,91.966) 105.741,91.12 ; 106.233,90.712 106.233,90.612 ; 106.244,90.707 ccw(c106.858,91.966) 106.498,90.612 ; 106.496,90.613 ccw(c106.858,91.966) 106.498,90.612 ; 106.519,90.606 cw(c106.858,91.966) 106.498,90.612 ; 106.785,90.567 cw(c106.858,91.966) 106.741,90.57 ; 106.798,90.571 ccw(c107.777,90.362) 106.776,90.362 106.776,90.104 ; 107.932,92.867 ccw(c106.858,91.966) 107.759,93.04 ccw(c106.858,91.966) 107.757,93.042 ; 107.933,92.869 cw(c109.258,93.325) 107.867,93.152 ; 108.096,91.308 ccw(c106.858,91.966) 108.218,91.627 ; 108.103,91.309 cw(c107.777,90.362) 108.265,91.237 ; 108.184,92.423 cw(c106.858,91.966) 108.25,92.136 ; 108.184,92.424 ccw(c109.258,93.325) 108.265,92.336 ; 109.347,90.104 109.281,90.104 ; 110.378,94.168 ccw(c109.258,93.325) 110.297,94.266 ; 110.805,92.814 cw(c112.075,93.406) 110.695,93.649 cw(c112.075,93.406) 110.697,93.66 ; 110.805,93.998 ccw(c112.075,93.406) 110.697,93.66 ; 111.174,92.332 cw(c112.075,93.406) 110.899,92.644 ; 111.183,92.325 111.183,92.136 ; 111.312,94.581 ccw(c112.075,93.406) 110.899,94.168 ; 111.313,94.582 111.313,94.676 ; 111.332,94.595 cw(c112.075,93.406) 111.482,94.676 ; 111.808,94.782 cw(c112.075,93.406) 111.821,94.784 ; 111.832,94.786 ccw(c112.075,93.406) 111.821,94.784 ; 112.318,94.786 ccw(c112.075,93.406) 111.821,94.784 ; 112.329,94.784 112.329,95.184 ; 112.342,94.782 cw(c112.075,93.406) 112.668,94.676 ; 113.25,92.642 113.345,92.642 ; 113.251,92.643 ccw(c112.075,93.406) 113.251,92.644 ; 113.345,93.998 cw(c112.075,93.406) 113.453,93.66 ; 113.451,93.673 cw(c112.075,93.406) 113.453,93.66 ; 113.455,93.649 ccw(c112.075,93.406) 113.453,93.66 ; 113.662,70.358 cw(c113.576,69.379) 113.668,70.357 ; 113.862,92.632 cw(c114.506,91.891) 113.873,92.642 ; pad.@114.094,68.025 pad.@114.361,68.025 ; 114.353,92.861 ccw(c114.506,91.891) 113.876,92.644 ; 114.361,92.862 114.361,93.152 ; 114.37,92.864 cw(c114.506,91.891) 114.869,92.804 ; 114.858,92.808 cw(c114.506,91.891) 114.869,92.804 ; 114.874,92.802 ccw(c114.506,91.891) 114.869,92.804 ; 115.07,92.695 ccw(c114.506,91.891) 114.869,92.804 ; 115.075,92.692 115.377,92.692 ; 117.916,93.856 cw(c119.314,93.954) 117.917,94.067 ; 117.917,93.841 117.917,93.66 ; 117.918,93.832 ccw(c119.314,93.954) 117.944,93.66 ; 118.413,95.028 cw(c119.314,93.954) 118.425,95.038 ; 118.432,95.043 ccw(c119.314,93.954) 118.425,95.038 ; 118.722,92.684 cw(c119.314,93.954) 118.704,92.692 ; 119.436,95.35 ccw(c119.314,93.954) 118.933,95.303 ; 119.441,95.35 119.441,95.692 ; 119.461,95.348 cw(c119.314,93.954) 119.949,95.204 ; 120.515,94.676 ccw(c119.314,93.954) 120.511,94.683 ; 121.981,67.107 121.981,67.244 ; 122.064,67.024 121.922,67.166 ; 123.383,90.675 cw(c122.408,90.795) 123.373,90.612 ; 123.384,90.679 123.505,90.801 ; 123.773,88.072 124.013,88.072 ; 123.9,94.168 124.013,94.168 ; 124.013,94.055 124.013,94.168 ; 124.335,68.957 124.013,68.957 ; 124.336,68.959 cw(c124.994,68.228) 124.518,69.088 cw(c124.994,68.228) 124.521,69.09 ; 124.589,87.934 124.521,87.934 ; 124.591,87.935 cw(c125.249,87.205) 124.786,88.072 ; 124.63,65.253 ccw(c123.911,65.923) pad.@124.872,65.72 ; 124.639,66.583 ccw(c124.133,67.425) 124.833,66.736 ; 124.641,66.58 cw(c123.911,65.923) 124.845,66.228 ; 125.028,69.21 ccw(c124.994,68.228) 124.521,69.09 ; 125.097,67.251 ccw(c124.994,68.228) 125.1,67.252 ; 125.1,67.254 cw(c124.133,67.425) 125.1,67.252 ; 125.529,67.404 cw(c124.994,68.228) 125.1,67.252 ; 125.537,67.41 125.537,67.244 ; 125.543,67.414 ccw(c124.994,68.228) 125.853,67.752 ; 125.917,67.892 ccw(c124.994,68.228) 125.918,67.895 ; pad.@125.917,68.564 cw(c124.994,68.228) pad.@125.918,68.562 ; 126.044,87.783 ccw(c125.249,87.205) 125.711,88.072 ; 126.045,87.781 126.045,88.072 ; 126.054,87.769 cw(c125.249,87.205) 126.163,87.564 ; 126.073,86.67 ccw(c125.249,87.205) 126.076,86.675 ; 126.108,86.729 ccw(c125.249,87.205) 126.112,86.735 ; 126.216,87.376 cw(c125.249,87.205) 126.217,87.374 ; 126.751,64.633 ccw(c126.222,63.389) 126.74,64.637 ; 127.061,85.786 127.061,86.04 ; 127.101,85.746 126.807,86.04 ; 127.104,85.748 cw(c127.709,84.974) 127.569,85.946 ; 127.557,63.178 ccw(c126.222,63.389) 127.558,63.18 ; 127.696,82.484 127.569,82.484 ; 128.058,67.234 ccw(c129.41,67.234) 128.077,67.009 ; 128.058,67.244 127.569,67.244 ; 128.058,67.257 cw(c129.41,67.234) 128.077,67.459 ; 128.578,66.169 ccw(c129.41,67.234) 128.585,66.163 ; 128.596,66.154 cw(c129.41,67.234) 128.585,66.163 ; 128.606,84.574 ccw(c127.709,84.974) 128.608,84.577 ; 128.669,84.516 129.093,84.516 ; 128.69,85.025 ccw(c127.709,84.974) 128.585,85.418 ; 129.018,69.661 ccw(c129.983,69.848) 129.019,69.657 ; 129.093,81.087 129.093,80.96 ; 129.22,80.96 129.093,80.96 ; 129.567,88.94 cw(c129.091,89.799) 129.093,88.816 ; 129.567,90.658 ccw(c129.091,89.799) 129.093,90.782 ; 129.574,88.943 129.601,88.943 ; 129.574,90.655 129.601,90.655 ; 129.601,80.579 129.601,80.452 ; 129.728,80.452 129.601,80.452 ; 130.109,72.01 130.109,72.324 ; 130.109,80.071 130.109,79.944 ; 130.236,79.944 130.109,79.944 ; 130.713,69.191 ccw(c129.983,69.848) 130.781,69.276 ; 130.787,70.412 cw(c129.983,69.848) 130.79,70.409 ; 130.944,69.644 cw(c129.983,69.848) 130.781,69.276 ; 132.522,69.276 132.141,69.276 ; 133.03,69.784 132.649,69.784 ; 133.123,71.274 133.03,71.181 132.649,71.181 ; 133.127,80.058 132.733,80.452 ; 133.13,71.275 ccw(c132.977,72.246) 133.157,71.28 ; 133.157,69.911 133.157,70.292 ; 133.284,79.842 133.284,79.944 ; 133.423,73.121 cw(c132.977,72.246) 133.429,73.118 ; 133.538,70.292 133.157,70.292 ; 133.665,70.419 133.665,70.8 ; 133.813,62.161 cw(c134.341,60.917) 133.82,62.164 ; 133.86,71.815 cw(c132.977,72.246) 133.665,71.545 ; 134.046,70.8 133.665,70.8 ; 134.173,70.927 134.173,71.308 ; 134.554,71.308 134.173,71.308 ; 134.681,71.435 134.681,71.816 ; 134.869,62.161 ccw(c134.341,60.917) 134.862,62.164 ; 136.992,90.655 136.713,90.655 ; 137.022,90.685 137.221,90.884 ; 137.426,85.051 cw(c138.451,84.095) 137.43,85.055 ; 137.729,85.296 cw(c138.451,84.095) 138.056,85.44 ; 137.816,91.479 137.729,91.392 ; 137.98,87.82 137.729,87.569 ; 137.981,87.822 138.232,88.072 ; 138.059,85.43 cw(c138.999,85.717) 138.056,85.44 ; 138.065,85.442 ccw(c138.451,84.095) 138.056,85.44 ; 138.28,87.546 cw(c139.634,87.183) 138.285,87.564 ; 138.287,87.569 ccw(c139.634,87.183) 138.285,87.564 ; 138.408,86.502 ccw(c138.999,85.717) pad.@138.237,86.338 ; 138.408,86.503 cw(c139.634,87.183) 138.385,86.548 ; 138.545,88.065 ccw(c139.634,87.183) 138.285,87.564 ; 138.55,88.072 138.237,88.072 ; 138.56,88.084 cw(c139.634,87.183) 138.745,88.267 ; 138.819,88.666 ccw(c139.634,89.215) 138.822,88.662 ; 138.904,88.558 cw(c139.634,89.215) 138.884,88.58 ; 138.905,88.556 138.905,88.38 ; 138.912,88.384 ccw(c139.634,87.183) 138.905,88.38 ; 139.938,61.653 ccw(c141.072,60.917) 139.761,61.246 ; 139.94,61.656 139.761,61.656 ; 139.951,61.673 cw(c141.072,60.917) 140.269,62.004 ; 140.259,59.538 cw(c141.072,60.617) 140.155,59.624 ; 140.259,61.996 cw(c141.072,60.917) 140.269,62.004 ; 140.269,59.53 140.269,59.116 ; 140.278,59.524 ccw(c141.072,60.617) 140.777,59.298 ; 140.278,62.01 ccw(c141.072,60.917) 140.269,62.004 ; 140.356,88.384 cw(c139.634,87.183) 140.363,88.38 ; 140.363,88.556 140.363,88.38 ; 140.364,88.558 ccw(c139.634,89.215) 140.384,88.58 ; 140.615,89.225 ccw(c140.242,90.524) 140.777,89.283 ; 140.617,89.215 cw(c139.634,89.215) 140.608,89.088 ; 140.768,59.3 ccw(c141.072,60.617) 140.777,59.298 ; 140.791,59.295 cw(c141.072,60.617) 140.777,59.298 ; 140.959,86.727 ccw(c139.634,87.183) 140.961,86.731 ; 141.318,73.085 ccw(c140.142,73.848) 141.318,73.086 ; 141.372,83.696 ccw(c140.65,84.897) 141.734,84.008 ; 141.382,83.681 cw(c140.598,82.519) 141.599,83.5 ; 141.391,74.484 cw(c140.142,73.848) 141.448,74.356 ; 141.402,74.486 ccw(c141.256,75.88) 141.793,74.585 ; 141.412,53.147 141.412,53.528 ; 141.46,53.103 ccw(c142.428,53.274) 141.479,53.02 ; 141.578,62.17 cw(c141.072,60.917) 141.593,62.164 ; 141.589,83.51 cw(c140.598,82.519) 141.599,83.5 ; 141.6,62.161 ccw(c141.072,60.917) 141.593,62.164 ; 141.606,83.493 ccw(c140.598,82.519) 141.599,83.5 ; 141.623,81.563 ccw(c140.598,82.519) 141.793,81.787 ; 141.64,81.556 cw(c140.777,80.452) 141.743,81.468 ; 141.774,79.482 cw(c141.031,78.293) 141.842,79.436 ; 141.785,79.478 ccw(c140.777,80.452) 142.083,79.944 ; 141.835,77.145 ccw(c141.031,78.293) 142.115,77.404 ; 141.848,77.15 cw(c141.256,75.88) 142.221,76.896 ; 141.896,56.165 cw(c142.801,55.781) 141.901,56.175 ; 141.976,59.613 cw(c141.072,60.617) 141.793,59.474 ; 141.989,59.624 142.301,59.624 ; 141.994,59.629 ccw(c141.072,60.617) 142.301,60.055 ; 141.997,85.283 cw(c140.65,84.897) 142,85.273 ; 142.301,78.885 cw(c141.031,78.293) 142.427,78.42 ; 142.334,60.133 ccw(c141.072,60.617) 142.424,60.617 142.424,60.64 ; 142.401,56.679 ccw(c142.801,55.781) 142.301,56.627 ; 142.406,56.681 142.809,57.084 ; 143.046,52.51 cw(c142.428,53.274) 142.812,52.37 cw(c142.428,53.274) 142.809,52.368 ; 143.048,52.512 143.317,52.512 ; 143.412,85.273 143.317,85.273 ; 143.415,85.268 ccw(c144.396,85.32) 143.459,85.024 ; 143.429,63.697 cw(c144.346,64.049) 143.375,64.196 ; 143.432,63.688 143.317,63.688 ; 143.435,63.681 ccw(c144.346,64.049) 143.618,63.389 ; 143.628,63.379 cw(c144.346,64.049) 143.618,63.389 ; 143.702,64.79 ccw(c144.346,64.049) 143.698,64.787 ; 144.333,86.413 144.333,86.548 ; 144.445,86.301 144.229,86.517 ; 144.447,86.301 cw(c144.396,85.32) 144.841,86.196 144.841,86.548 ; 144.842,86.195 cw(c144.396,85.32) 145.064,86.04 ; 146.419,73.213 146.365,73.213 ; 146.422,73.214 cw(c146.709,72.274) 146.873,73.243 ; 146.997,73.214 ccw(c146.709,72.274) 146.873,73.243 ; 147,73.213 147.381,73.213 ; 171.003,105.947 171.003,105.852 ; 171.003,107.54 171.003,108.392 ; 171.003,107.884 171.257,107.884 ; 171.005,105.949 ccw(c170.428,106.744) 171.257,106.216 ; 171.005,107.539 cw(c170.428,106.744) 171.18,107.376 ; 172.807,103.667 172.781,103.693 ; 172.821,103.667 173.289,103.667 ; 173.653,106.162 ccw(c173.924,105.217) 173.289,105.967 ; 173.661,106.164 173.797,106.3 ; 174.339,104.326 ccw(c173.924,105.217) 174.343,104.328 ; 174.355,104.334 cw(c173.924,105.217) 174.343,104.328 ; 174.869,104.946 cw(c173.924,105.217) 174.83,104.836 ; 174.871,104.954 175.261,105.344 ; 176.502,103.27 176.845,102.927 ; 178.783,105.231 178.783,104.836 ; 178.783,105.233 cw(c179.68,105.633) 178.741,105.344 ; 178.785,103.065 ccw(c179.503,102.395) 178.783,103.064 ; 180.486,102.395 cw(c179.503,102.395) 180.481,102.296 ; 180.495,105.083 180.495,104.836 ; 180.495,105.083 ccw(c179.68,105.633) 180.619,105.344 ; 180.999,109.689 cw(c181.253,110.638) 180.99,109.692 ; 181.344,113.425 ccw(c182.433,112.543) 181.341,113.421 ; 181.375,111.623 cw(c182.433,112.543) 181.164,111.948 ; 181.39,111.611 ccw(c181.253,110.638) 180.909,111.559 ; 182.433,98.09 ccw(c183.195,97.47) 182.246,97.724 ; 182.502,104.7 182.433,104.769 ; 182.504,104.692 ccw(c183.449,104.963) 182.699,104.328 ; 182.538,98.2 ccw(c183.195,97.47) 182.433,98.09 182.433,98.232 ; 182.541,98.206 cw(c183.356,98.756) 182.524,98.232 ; 182.696,104.331 ccw(c183.449,104.963) 182.699,104.328 ; 182.707,104.318 cw(c183.449,104.963) 182.699,104.328 ; 183.168,99.72 ccw(c183.356,98.756) 182.941,99.646 ; 183.703,105.912 cw(c183.449,104.963) 183.712,105.91 ; 184.143,97.212 184.465,97.212 ; 184.176,97.419 cw(c183.195,97.47) 184.144,97.216 184.465,97.216 ; 184.176,97.421 184.386,97.63 184.465,97.63 ; 190.561,97.888 190.561,97.724 ; 191.795,99.122 191.577,98.904 ; 191.801,99.118 ccw(c192.336,99.942) 192.085,98.992 ; 192.081,98.993 ccw(c192.336,99.942) 192.085,98.992 ; 192.098,98.989 cw(c192.336,99.942) 192.085,98.992 ; 193.259,99.606 cw(c192.336,99.942) 193.101,99.326 ; 193.262,99.613 193.609,99.613 ; 194.269,101.882 194.117,101.882 ; 194.276,101.885 cw(c194.752,101.026) 194.625,102 ; 195.734,101.071 196.149,101.071 ; 195.733,101.077 ccw(c194.752,101.026) 195.701,101.28 ; 198.561,105.886 198.181,105.886 ; 198.769,101.071 198.689,101.071 ; 198.771,101.076 cw(c199.705,100.772) 198.863,101.278 cw(c199.705,100.772) 198.864,101.28 ; 199.739,101.754 cw(c199.705,100.772) 200.211,101.614 cw(c199.705,100.772) 200.213,101.613 ; 199.756,99.791 ccw(c199.705,100.772) 200.211,99.93 ccw(c199.705,100.772) 200.213,99.931 ; 199.756,101.753 ccw(c199.705,100.772) 199.705,101.755 ; 200.645,101.059 cw(c199.705,100.772) 200.688,100.772 ; 200.65,101.043 ccw(c199.705,100.772) 200.547,101.278 ccw(c199.705,100.772) 200.546,101.28 ; 211.457,105.886 211.897,105.886 ; 211.577,105.784 211.897,105.464 ; 213.407,98.56 cw(c213.548,97.216) 213.421,98.562 ; 213.421,103.94 213.421,104.328 ; 213.43,98.562 ccw(c213.548,97.216) 213.421,98.562 ; 213.541,103.82 213.929,103.82 ; 213.607,103.754 213.033,104.328 ; 214.801,96.71 ccw(c213.548,97.216) 214.9,97.216 ; 217.485,108.286 217.485,107.884 ; 219.554,97.147 ccw(c220.519,95.997) 219.547,97.141 ; 219.622,97.216 219.517,97.216 ; 220.518,100.066 cw(c221.422,98.867) 220.533,100.077 ; 220.539,100.082 ccw(c221.422,98.867) 220.533,100.077 ; 222.057,100.228 ccw(c221.422,98.867) 221.973,100.264 ; 224.597,96.962 224.597,97.216 ; 224.851,108.392 224.597,108.392 ; 225.105,108.138 225.105,107.884 ; 225.359,107.884 225.105,107.884 ; 225.613,97.978 pad.@225.613,98.232 ; 226.121,98.74 225.613,98.74 ; 226.121,99.781 226.121,100.264 ; 20.763,55.052 20.889,55.052 ; 20.763,55.052 20.762,55.179 20.889,55.382 ; 20.763,55.052 20.765,54.544 ; 20.765,54.544 20.767,54.036 ; 20.765,54.544 20.889,54.544 ; 20.767,54.036 20.77,53.528 ; 20.767,54.036 20.889,54.036 ; 20.77,53.528 20.772,53.02 ; 20.77,53.528 20.889,53.528 ; 20.772,53.02 20.889,53.02 ; 20.772,53.02 20.774,52.512 ; 20.774,52.512 20.889,52.512 ; 20.774,52.512 20.777,52.004 ; 20.777,52.004 20.889,52.004 ; 20.777,52.004 20.779,51.496 ; 20.779,51.496 20.889,51.496 ; 20.779,51.496 20.782,50.988 ; 20.782,50.988 pad.@20.889,50.988 ; 20.782,50.988 20.783,50.724 20.784,50.48 ; 20.784,50.48 pad.@20.889,50.48 ; 20.784,50.48 20.786,49.972 ; 20.786,49.972 20.889,49.972 ; 20.786,49.972 20.789,49.464 ; 20.789,49.464 20.791,48.956 ; 20.789,49.464 20.889,49.464 ; 20.791,48.956 20.889,48.956 ; 20.791,48.956 20.793,48.448 ; 20.793,48.448 20.889,48.448 ; 20.793,48.448 20.796,47.94 ; 20.796,47.94 20.889,47.94 ; 20.796,47.94 20.798,47.432 ; 20.798,47.432 20.889,47.432 ; 20.798,47.432 20.8,46.924 ; 20.8,46.924 20.889,46.924 ; 20.8,46.924 20.803,46.416 ; 20.803,46.416 20.889,46.416 ; 20.803,46.416 20.805,45.908 ; 20.805,45.908 20.889,45.908 ; 20.805,45.908 20.808,45.4 ; 20.808,45.4 20.889,45.4 ; 20.808,45.4 pad.@20.81,44.892 ; pad.@20.81,44.892 pad.@20.889,44.892 ; pad.@20.81,44.892 20.81,44.803 20.812,44.384 ; 20.812,44.384 20.889,44.384 ; 20.812,44.384 20.815,43.876 ; 20.815,43.876 20.889,43.876 ; 20.815,43.876 20.817,43.368 ; 20.817,43.368 20.889,43.368 ; 20.817,43.368 20.819,42.86 ; 20.819,42.86 20.822,42.352 ; 20.819,42.86 20.889,42.86 ; 20.822,42.352 20.889,42.352 ; 20.822,42.352 20.824,41.844 ; 20.824,41.844 20.889,41.844 ; 20.824,41.844 20.826,41.336 ; 20.826,41.336 20.889,41.336 ; 20.826,41.336 20.829,40.828 ; 20.829,40.828 20.889,40.828 ; 20.829,40.828 20.831,40.32 ; 20.831,40.32 20.889,40.32 ; 20.831,40.32 20.833,39.812 ; 20.833,39.812 20.889,39.812 ; 20.833,39.812 20.836,39.304 ; 20.836,39.304 20.889,39.304 ; 20.836,39.304 20.838,38.865 pad.@20.838,38.796 ; pad.@20.838,38.796 pad.@20.889,38.796 ; pad.@20.838,38.796 20.841,38.288 ; 20.841,38.288 20.889,38.288 ; 20.841,38.288 20.843,37.78 ; 20.843,37.78 20.889,37.78 ; 20.843,37.78 20.845,37.272 ; 20.845,37.272 20.889,37.272 ; 20.845,37.272 20.848,36.764 ; 20.848,36.764 20.889,36.764 ; 20.848,36.764 20.85,36.256 ; 20.85,36.256 20.889,36.256 ; 20.85,36.256 20.852,35.748 ; 20.852,35.748 20.889,35.748 ; 20.852,35.748 20.855,35.24 ; 20.855,35.24 20.889,35.24 ; 20.855,35.24 20.856,34.871 pad.@20.857,34.732 ; pad.@20.857,34.732 pad.@20.889,34.732 ; pad.@20.857,34.732 20.859,34.224 ; 20.859,34.224 20.889,34.224 ; 20.859,34.224 20.862,33.716 ; 20.862,33.716 20.889,33.716 ; 20.862,33.716 20.864,33.208 ; 20.864,33.208 20.889,33.208 ; 20.864,33.208 20.867,32.7 ; 20.867,32.7 20.889,32.7 ; 20.867,32.7 20.869,32.192 ; 20.869,32.192 20.889,32.192 ; 20.869,32.192 20.871,31.684 ; 20.871,31.684 20.889,31.684 ; 20.871,31.684 20.874,31.176 ; 20.874,31.176 20.889,31.176 ; 20.874,31.176 20.876,30.668 ; 20.876,30.668 20.878,30.16 ; 20.876,30.668 20.889,30.668 ; 20.878,30.16 20.889,30.16 ; 20.878,30.16 20.881,29.652 ; 20.881,29.652 20.889,29.652 ; 20.881,29.652 20.883,29.144 ; 20.883,29.144 20.889,29.144 ; 20.883,29.144 20.885,28.636 ; 20.885,28.636 20.889,28.636 ; 20.885,28.636 20.888,28.128 20.889,27.874 21.143,27.62 ; 20.889,28.128 20.889,28.636 ; 20.889,28.128 21.397,28.128 ; 20.889,28.636 20.889,29.144 ; 20.889,28.636 21.397,28.636 ; 20.889,29.144 20.889,29.652 ; 20.889,29.144 21.397,29.144 ; 20.889,29.652 20.889,30.16 ; 20.889,29.652 21.397,29.652 ; 20.889,30.16 20.889,30.668 ; 20.889,30.16 21.397,30.16 ; 20.889,30.668 20.889,31.176 ; 20.889,30.668 21.397,30.668 ; 20.889,31.176 20.889,31.684 ; 20.889,31.176 21.397,31.176 ; 20.889,31.684 20.889,32.192 ; 20.889,31.684 21.397,31.684 ; 20.889,32.192 21.397,32.192 ; 20.889,32.192 20.889,32.7 ; 20.889,32.7 20.889,33.208 ; 20.889,32.7 21.397,32.7 ; 20.889,33.208 20.889,33.716 ; 20.889,33.208 21.397,33.208 ; 20.889,33.716 20.889,34.224 ; 20.889,33.716 21.397,33.716 ; 20.889,34.224 pad.@20.889,34.732 ; 20.889,34.224 21.397,34.224 ; pad.@20.889,34.732 pad.@21.397,34.732 ; pad.@20.889,34.732 20.889,35.24 ; 20.889,35.24 20.889,35.748 ; 20.889,35.24 21.397,35.24 ; 20.889,35.748 21.397,35.748 ; 20.889,35.748 20.889,36.256 ; 20.889,36.256 21.397,36.256 ; 20.889,36.256 20.889,36.764 ; 20.889,36.764 20.889,37.272 ; 20.889,36.764 21.397,36.764 ; 20.889,37.272 20.889,37.78 ; 20.889,37.272 21.397,37.272 ; 20.889,37.78 20.889,38.288 ; 20.889,37.78 21.397,37.78 ; 20.889,38.288 pad.@20.889,38.796 ; 20.889,38.288 21.397,38.288 ; pad.@20.889,38.796 pad.@21.397,38.796 ; pad.@20.889,38.796 20.889,39.304 ; 20.889,39.304 20.889,39.812 ; 20.889,39.304 21.397,39.304 ; 20.889,39.812 20.889,40.32 ; 20.889,39.812 21.397,39.812 ; 20.889,40.32 20.889,40.828 ; 20.889,40.32 21.397,40.32 ; 20.889,40.828 20.889,41.336 ; 20.889,40.828 21.397,40.828 ; 20.889,41.336 20.889,41.844 ; 20.889,41.336 21.397,41.336 ; 20.889,41.844 20.889,42.352 ; 20.889,41.844 21.397,41.844 ; 20.889,42.352 20.889,42.86 ; 20.889,42.352 21.397,42.352 ; 20.889,42.86 20.889,43.368 ; 20.889,42.86 21.397,42.86 ; 20.889,43.368 20.889,43.876 ; 20.889,43.368 21.397,43.368 ; 20.889,43.876 20.889,44.384 ; 20.889,43.876 21.397,43.876 ; 20.889,44.384 pad.@20.889,44.892 ; 20.889,44.384 21.397,44.384 ; pad.@20.889,44.892 20.889,45.4 ; pad.@20.889,44.892 pad.@21.397,44.892 ; 20.889,45.4 20.889,45.908 ; 20.889,45.4 21.397,45.4 ; 20.889,45.908 20.889,46.416 ; 20.889,45.908 21.397,45.908 ; 20.889,46.416 20.889,46.924 ; 20.889,46.416 21.397,46.416 ; 20.889,46.924 20.889,47.432 ; 20.889,46.924 21.397,46.924 ; 20.889,47.432 20.889,47.94 ; 20.889,47.432 21.397,47.432 ; 20.889,47.94 20.889,48.448 ; 20.889,47.94 21.397,47.94 ; 20.889,48.448 20.889,48.956 ; 20.889,48.448 21.397,48.448 ; 20.889,48.956 20.889,49.464 ; 20.889,48.956 21.397,48.956 ; 20.889,49.464 20.889,49.972 ; 20.889,49.464 21.397,49.464 ; 20.889,49.972 pad.@20.889,50.48 ; 20.889,49.972 21.397,49.972 ; pad.@20.889,50.48 pad.@20.889,50.988 ; pad.@20.889,50.48 21.397,50.48 ; pad.@20.889,50.988 20.889,51.496 ; pad.@20.889,50.988 21.397,50.988 ; 20.889,51.496 20.889,52.004 ; 20.889,51.496 21.397,51.496 ; 20.889,52.004 20.889,52.512 ; 20.889,52.004 21.397,52.004 ; 20.889,52.512 20.889,53.02 ; 20.889,52.512 21.397,52.512 ; 20.889,53.02 20.889,53.528 ; 20.889,53.02 21.397,53.02 ; 20.889,53.528 21.397,53.528 ; 20.889,53.528 20.889,54.036 ; 20.889,54.036 21.397,54.036 ; 20.889,54.036 20.889,54.544 ; 20.889,54.544 20.889,55.052 ; 20.889,54.544 21.397,54.544 ; 20.889,55.052 20.889,55.382 ; 20.889,55.052 21.397,55.052 ; 20.889,55.382 21,55.56 ; 21,55.56 pad.@21.397,55.56 ; 21,55.56 21.397,56.195 ; 21.143,27.62 21.397,27.366 ; 21.143,27.62 21.397,27.62 ; 21.397,27.366 21.651,27.112 ; 21.397,27.366 21.397,27.62 ; 21.397,27.62 21.397,28.128 ; 21.397,27.62 21.905,27.62 ; 21.397,28.128 21.397,28.636 ; 21.397,28.128 21.905,28.128 ; 21.397,28.636 21.397,29.144 ; 21.397,28.636 21.905,28.636 ; 21.397,29.144 21.397,29.652 ; 21.397,29.144 21.905,29.144 ; 21.397,29.652 21.397,30.16 ; 21.397,29.652 21.905,29.652 ; 21.397,30.16 21.397,30.668 ; 21.397,30.16 21.905,30.16 ; 21.397,30.668 21.397,31.176 ; 21.397,30.668 21.905,30.668 ; 21.397,31.176 21.397,31.684 ; 21.397,31.176 21.905,31.176 ; 21.397,31.684 21.397,32.192 ; 21.397,31.684 21.905,31.684 ; 21.397,32.192 21.905,32.192 ; 21.397,32.192 21.397,32.7 ; 21.397,32.7 21.397,33.208 ; 21.397,32.7 21.905,32.7 ; 21.397,33.208 21.397,33.716 ; 21.397,33.208 21.905,33.208 ; 21.397,33.716 21.397,34.224 ; 21.397,33.716 21.905,33.716 ; 21.397,34.224 pad.@21.397,34.732 ; 21.397,34.224 21.905,34.224 ; pad.@21.397,34.732 21.905,34.732 ; pad.@21.397,34.732 21.397,35.24 ; 21.397,35.24 21.905,35.24 ; 21.397,35.24 21.397,35.748 ; 21.397,35.748 21.905,35.748 ; 21.397,35.748 21.397,36.256 ; 21.397,36.256 21.905,36.256 ; 21.397,36.256 21.397,36.764 ; 21.397,36.764 21.397,37.272 ; 21.397,36.764 21.905,36.764 ; 21.397,37.272 21.397,37.78 ; 21.397,37.272 21.905,37.272 ; 21.397,37.78 21.397,38.288 ; 21.397,37.78 21.905,37.78 ; 21.397,38.288 pad.@21.397,38.796 ; 21.397,38.288 21.905,38.288 ; pad.@21.397,38.796 21.905,38.796 ; pad.@21.397,38.796 21.397,39.304 ; 21.397,39.304 21.397,39.812 ; 21.397,39.304 21.905,39.304 ; 21.397,39.812 21.397,40.32 ; 21.397,39.812 21.905,39.812 ; 21.397,40.32 21.397,40.828 ; 21.397,40.32 21.905,40.32 ; 21.397,40.828 21.397,41.336 ; 21.397,40.828 21.905,40.828 ; 21.397,41.336 21.397,41.844 ; 21.397,41.336 21.905,41.336 ; 21.397,41.844 21.397,42.352 ; 21.397,41.844 21.905,41.844 ; 21.397,42.352 21.397,42.86 ; 21.397,42.352 21.905,42.352 ; 21.397,42.86 21.397,43.368 ; 21.397,42.86 21.905,42.86 ; 21.397,43.368 21.397,43.876 ; 21.397,43.368 21.905,43.368 ; 21.397,43.876 21.397,44.384 ; 21.397,43.876 21.905,43.876 ; 21.397,44.384 21.905,44.384 ; 21.397,44.384 pad.@21.397,44.892 ; pad.@21.397,44.892 21.397,45.4 ; pad.@21.397,44.892 21.905,44.892 ; 21.397,45.4 21.397,45.908 ; 21.397,45.4 21.905,45.4 ; 21.397,45.908 21.397,46.416 ; 21.397,45.908 21.905,45.908 ; 21.397,46.416 21.397,46.924 ; 21.397,46.416 21.905,46.416 ; 21.397,46.924 21.397,47.432 ; 21.397,46.924 21.905,46.924 ; 21.397,47.432 21.397,47.94 ; 21.397,47.432 21.905,47.432 ; 21.397,47.94 21.397,48.448 ; 21.397,47.94 21.905,47.94 ; 21.397,48.448 21.397,48.956 ; 21.397,48.448 21.905,48.448 ; 21.397,48.956 21.397,49.464 ; 21.397,48.956 21.905,48.956 ; 21.397,49.464 21.397,49.972 ; 21.397,49.464 21.905,49.464 ; 21.397,49.972 21.397,50.48 ; 21.397,49.972 21.905,49.972 ; 21.397,50.48 21.905,50.48 ; 21.397,50.48 21.397,50.988 ; 21.397,50.988 21.397,51.496 ; 21.397,50.988 21.905,50.988 ; 21.397,51.496 21.397,52.004 ; 21.397,51.496 21.905,51.496 ; 21.397,52.004 21.397,52.512 ; 21.397,52.004 21.905,52.004 ; 21.397,52.512 21.397,53.02 ; 21.397,52.512 21.905,52.512 ; 21.397,53.02 21.397,53.528 ; 21.397,53.02 21.905,53.02 ; 21.397,53.528 21.397,54.036 ; 21.397,53.528 21.905,53.528 ; 21.397,54.036 21.397,54.544 ; 21.397,54.036 21.905,54.036 ; 21.397,54.544 21.397,55.052 ; 21.397,54.544 21.905,54.544 ; 21.397,55.052 pad.@21.397,55.56 ; 21.397,55.052 21.905,55.052 ; pad.@21.397,55.56 21.397,56.068 ; pad.@21.397,55.56 pad.@21.905,55.56 ; 21.397,56.068 21.397,56.195 ; 21.397,56.068 21.905,56.068 ; 21.397,56.195 21.905,56.193 ; 21.651,27.112 21.905,26.858 ; 21.651,27.112 pad.@21.905,27.112 ; 21.905,26.858 22.032,26.731 pad.@22.413,26.731 ; 21.905,26.858 pad.@21.905,27.112 ; pad.@21.905,27.112 21.905,27.62 ; pad.@21.905,27.112 pad.@22.413,27.112 ; 21.905,27.62 21.905,28.128 ; 21.905,27.62 22.413,27.62 ; 21.905,28.128 21.905,28.636 ; 21.905,28.128 22.413,28.128 ; 21.905,28.636 21.905,29.144 ; 21.905,28.636 22.413,28.636 ; 21.905,29.144 21.905,29.652 ; 21.905,29.144 22.413,29.144 ; 21.905,29.652 21.905,30.16 ; 21.905,29.652 22.413,29.652 ; 21.905,30.16 21.905,30.668 ; 21.905,30.16 22.413,30.16 ; 21.905,30.668 21.905,31.176 ; 21.905,30.668 22.413,30.668 ; 21.905,31.176 21.905,31.684 ; 21.905,31.176 22.413,31.176 ; 21.905,31.684 21.905,32.192 ; 21.905,31.684 22.413,31.684 ; 21.905,32.192 22.413,32.192 ; 21.905,32.192 21.905,32.7 ; 21.905,32.7 21.905,33.208 ; 21.905,32.7 22.413,32.7 ; 21.905,33.208 21.905,33.716 ; 21.905,33.208 22.413,33.208 ; 21.905,33.716 21.905,34.224 ; 21.905,33.716 22.413,33.716 ; 21.905,34.224 21.905,34.732 ; 21.905,34.224 22.413,34.224 ; 21.905,34.732 22.413,34.732 ; 21.905,34.732 21.905,35.24 ; 21.905,35.24 22.413,35.24 ; 21.905,35.24 21.905,35.748 ; 21.905,35.748 22.413,35.748 ; 21.905,35.748 21.905,36.256 ; 21.905,36.256 22.413,36.256 ; 21.905,36.256 21.905,36.764 ; 21.905,36.764 21.905,37.272 ; 21.905,36.764 22.413,36.764 ; 21.905,37.272 21.905,37.78 ; 21.905,37.272 22.413,37.272 ; 21.905,37.78 21.905,38.288 ; 21.905,37.78 22.413,37.78 ; 21.905,38.288 21.905,38.796 ; 21.905,38.288 22.413,38.288 ; 21.905,38.796 21.905,39.304 ; 21.905,38.796 22.413,38.796 ; 21.905,39.304 21.905,39.812 ; 21.905,39.304 22.413,39.304 ; 21.905,39.812 21.905,40.32 ; 21.905,39.812 22.413,39.812 ; 21.905,40.32 21.905,40.828 ; 21.905,40.32 22.413,40.32 ; 21.905,40.828 21.905,41.336 ; 21.905,40.828 22.413,40.828 ; 21.905,41.336 21.905,41.844 ; 21.905,41.336 22.413,41.336 ; 21.905,41.844 21.905,42.352 ; 21.905,41.844 22.413,41.844 ; 21.905,42.352 21.905,42.86 ; 21.905,42.352 22.413,42.352 ; 21.905,42.86 21.905,43.368 ; 21.905,42.86 22.413,42.86 ; 21.905,43.368 21.905,43.876 ; 21.905,43.368 22.413,43.368 ; 21.905,43.876 21.905,44.384 ; 21.905,43.876 22.413,43.876 ; 21.905,44.384 21.905,44.892 ; 21.905,44.384 22.413,44.384 ; 21.905,44.892 21.905,45.4 ; 21.905,44.892 22.413,44.892 ; 21.905,45.4 21.905,45.908 ; 21.905,45.4 22.413,45.4 ; 21.905,45.908 21.905,46.416 ; 21.905,45.908 22.413,45.908 ; 21.905,46.416 21.905,46.924 ; 21.905,46.416 22.413,46.416 ; 21.905,46.924 21.905,47.432 ; 21.905,46.924 22.413,46.924 ; 21.905,47.432 21.905,47.94 ; 21.905,47.432 22.413,47.432 ; 21.905,47.94 21.905,48.448 ; 21.905,47.94 22.413,47.94 ; 21.905,48.448 21.905,48.956 ; 21.905,48.448 22.413,48.448 ; 21.905,48.956 21.905,49.464 ; 21.905,48.956 22.413,48.956 ; 21.905,49.464 21.905,49.972 ; 21.905,49.464 22.413,49.464 ; 21.905,49.972 21.905,50.48 ; 21.905,49.972 22.413,49.972 ; 21.905,50.48 21.905,50.988 ; 21.905,50.48 22.413,50.48 ; 21.905,50.988 21.905,51.496 ; 21.905,50.988 22.413,50.988 ; 21.905,51.496 21.905,52.004 ; 21.905,51.496 22.413,51.496 ; 21.905,52.004 21.905,52.512 ; 21.905,52.004 22.413,52.004 ; 21.905,52.512 21.905,53.02 ; 21.905,52.512 22.413,52.512 ; 21.905,53.02 21.905,53.528 ; 21.905,53.02 22.413,53.02 ; 21.905,53.528 21.905,54.036 ; 21.905,53.528 22.413,53.528 ; 21.905,54.036 21.905,54.544 ; 21.905,54.036 22.413,54.036 ; 21.905,54.544 21.905,55.052 ; 21.905,54.544 22.413,54.544 ; 21.905,55.052 22.413,55.052 ; 21.905,55.052 pad.@21.905,55.56 ; pad.@21.905,55.56 21.905,56.068 ; pad.@21.905,55.56 22.413,55.56 ; 21.905,56.068 21.905,56.193 ; 21.905,56.068 22.413,56.068 ; 21.905,56.193 22.413,56.192 ; pad.@22.413,26.731 22.921,26.731 ; pad.@22.413,26.731 pad.@22.413,27.112 ; pad.@22.413,27.112 22.413,27.62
